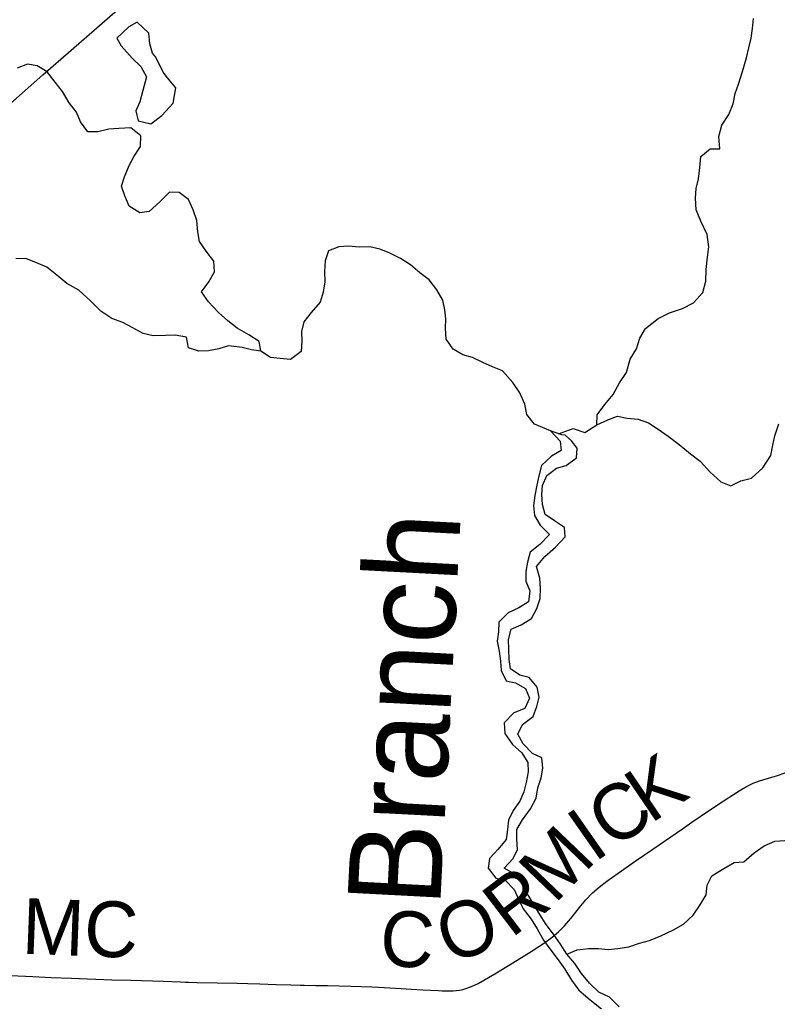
# Model space of a CAD drawing. Extents: x 0 to 34, y 0 to 22.
# Drawn here: x 26.924 to 27.697, y 10.604 to 11.606 of the extents above; entities that cross this region are included whole.
import ezdxf

# ---------------------------------------------------------------- set-up
doc = ezdxf.new("R2010")
doc.units = 0
for name, color, linetype in [('GM_X_County_Road', 7, 'Continuous'), ('GM_X_County_Road_Text', 7, 'Continuous'), ('GM_X_Minor_Lake', 7, 'Continuous'), ('GM_X_Minor_River', 7, 'Continuous'), ('GM_X_Minor_River_Text', 7, 'Continuous'), ('GM_X_Rail_Line', 7, 'Continuous')]:
    doc.layers.add(name, color=color, linetype=linetype)

msp = doc.modelspace()

# ---------------------------------------------------------------- linework, layer by layer
at = {"layer": 'GM_X_County_Road'}
msp.add_lwpolyline([(26.9075, 10.631), (26.938, 10.6298), (26.9565, 10.6289), (26.9772, 10.628), (27.0186, 10.6265), (27.0378, 10.6259), (27.0707, 10.625), (27.0887, 10.6243), (27.0937, 10.6241), (27.0967, 10.6241), (27.1054, 10.6237), (27.1463, 10.6229), (27.1572, 10.6227), (27.1696, 10.6222), (27.1863, 10.6215), (27.2012, 10.6212), (27.2105, 10.621), (27.2148, 10.6209), (27.2266, 10.6207), (27.2384, 10.6205), (27.2626, 10.62), (27.2837, 10.6192), (27.2905, 10.6189), (27.3135, 10.6176), (27.324, 10.6169), (27.3358, 10.6162), (27.3513, 10.6154), (27.3556, 10.6151), (27.3593, 10.615), (27.3627, 10.6151), (27.3666, 10.6152), (27.3699, 10.6154), (27.3732, 10.6158), (27.3766, 10.6164), (27.3798, 10.6175), (27.3855, 10.6196), (27.3921, 10.6228), (27.4093, 10.6325), (27.4214, 10.6399), (27.432, 10.6464), (27.4463, 10.6552), (27.4588, 10.6633), (27.4677, 10.6699), (27.4743, 10.6755), (27.4804, 10.6816), (27.4868, 10.6891), (27.4918, 10.6954), (27.4969, 10.7017), (27.5021, 10.7079), (27.509, 10.7151), (27.5156, 10.7209), (27.5234, 10.7271), (27.5351, 10.7353), (27.5442, 10.7418), (27.5523, 10.7475), (27.5703, 10.7597), (27.6006, 10.7804), (27.6102, 10.7872), (27.6282, 10.7995), (27.6422, 10.8087), (27.6584, 10.8193), (27.666, 10.8236), (27.6727, 10.8269), (27.6792, 10.8294), (27.6917, 10.8331), (27.6965, 10.8346), (27.7064, 10.8378)], dxfattribs=at)
at = {"layer": 'GM_X_Minor_Lake'}
msp.add_line((27.0707, 11.5522), (27.0633, 11.5677), dxfattribs=at)
msp.add_lwpolyline([(27.0633, 11.5677), (27.0598, 11.5718), (27.0571, 11.5813), (27.0562, 11.5919), (27.0443, 11.6032), (27.0357, 11.5985), (27.0237, 11.587), (27.0279, 11.579), (27.0391, 11.5666), (27.0479, 11.558), (27.0537, 11.5475), (27.05, 11.5337), (27.0471, 11.5219), (27.0431, 11.5128), (27.0455, 11.5026), (27.0584, 11.4997), (27.0696, 11.5082), (27.0812, 11.5208), (27.0837, 11.5364), (27.0753, 11.5466), (27.0707, 11.5522)], dxfattribs=at)
at = {"layer": 'GM_X_Minor_River'}
for points in [[(27.5133, 11.1925), (27.5136, 11.2028), (27.5214, 11.2131), (27.53, 11.2235), (27.5363, 11.2353), (27.5434, 11.246), (27.5474, 11.2594), (27.5537, 11.2701), (27.557, 11.2808), (27.5629, 11.2907), (27.5757, 11.3011), (27.5874, 11.3069), (27.6006, 11.3113), (27.6119, 11.3171), (27.6216, 11.3275), (27.6245, 11.3389), (27.6247, 11.351), (27.6261, 11.3636), (27.6275, 11.3742), (27.6259, 11.3867), (27.6193, 11.4003), (27.6146, 11.4117), (27.6141, 11.4238), (27.6147, 11.4337), (27.6169, 11.4436), (27.6183, 11.455), (27.6193, 11.4664), (27.629, 11.4741), (27.6389, 11.4742), (27.6376, 11.4867), (27.6409, 11.4981), (27.648, 11.5092), (27.6524, 11.5199), (27.6545, 11.5306), (27.6578, 11.5401), (27.6618, 11.5531), (27.6659, 11.5668), (27.6684, 11.577), (27.6709, 11.5869), (27.672, 11.5968), (27.673, 11.6071)], [(27.1705, 11.2675), (27.1688, 11.2774), (27.1581, 11.2844), (27.1463, 11.2911), (27.1368, 11.2986), (27.1272, 11.3072), (27.1172, 11.3181), (27.1099, 11.3283), (27.1174, 11.3383), (27.1233, 11.3486), (27.1225, 11.3596), (27.1148, 11.3697), (27.1078, 11.3795), (27.1062, 11.3894), (27.1053, 11.4008), (27.1014, 11.4117), (27.0967, 11.4223), (27.0872, 11.4294), (27.0773, 11.43), (27.0676, 11.4201), (27.0567, 11.4101), (27.0469, 11.4088), (27.0362, 11.4155), (27.0316, 11.4261), (27.0284, 11.4359), (27.0313, 11.4455), (27.0361, 11.4569), (27.0413, 11.4665), (27.0477, 11.4764), (27.0479, 11.4874), (27.038, 11.4956), (27.0255, 11.4947), (27.0153, 11.4942), (27.0043, 11.4915), (26.9941, 11.4913), (26.9864, 11.5015), (26.9825, 11.5113), (26.9748, 11.5211), (26.9682, 11.5324), (26.9606, 11.5422), (26.9525, 11.5527), (26.9422, 11.5587), (26.9323, 11.5605), (26.9218, 11.5565)], [(27.466, 11.1863), (27.4497, 11.1933), (27.442, 11.2031), (27.44, 11.2137), (27.4349, 11.225), (27.4276, 11.2356), (27.4169, 11.2476), (27.407, 11.2517), (27.3971, 11.2561), (27.3864, 11.2613), (27.3765, 11.2638), (27.3666, 11.2698), (27.3597, 11.28), (27.3588, 11.291), (27.3591, 11.3005), (27.3582, 11.3099), (27.3562, 11.3198), (27.35, 11.3303), (27.3423, 11.3405), (27.3328, 11.3476), (27.3232, 11.3559), (27.3129, 11.3622), (27.3015, 11.3681), (27.292, 11.3718), (27.2817, 11.374), (27.2707, 11.3738), (27.2601, 11.3749), (27.2499, 11.374), (27.2394, 11.3701), (27.2361, 11.3598), (27.2354, 11.3491), (27.2359, 11.3385), (27.2342, 11.3279), (27.2309, 11.3176), (27.2219, 11.3072), (27.2144, 11.2976), (27.2119, 11.2877), (27.2124, 11.2779), (27.2117, 11.2672), (27.2008, 11.2591), (27.1902, 11.2601), (27.1804, 11.2612), (27.1705, 11.2675), (27.161, 11.2689), (27.1515, 11.2715), (27.1374, 11.2732), (27.1276, 11.27), (27.117, 11.268), (27.1072, 11.2675), (27.0966, 11.2712), (27.0945, 11.2818), (27.0832, 11.284), (27.0733, 11.2835), (27.0608, 11.2833), (27.0506, 11.2858), (27.0391, 11.2918), (27.0296, 11.297), (27.0186, 11.301), (27.0071, 11.3085), (26.9968, 11.319), (26.9849, 11.3299), (26.9724, 11.3366), (26.9624, 11.3452), (26.9521, 11.3534), (26.9411, 11.3582), (26.9315, 11.3619), (26.9206, 11.3622)], [(27.4743, 11.1835), (27.4891, 11.1888), (27.5009, 11.1848), (27.5133, 11.1925), (27.5246, 11.1976), (27.5344, 11.2015), (27.5443, 11.1994), (27.5553, 11.1984), (27.5659, 11.1947), (27.5758, 11.188), (27.5861, 11.1809), (27.5972, 11.1726), (27.6087, 11.1629), (27.6186, 11.1554), (27.6286, 11.1445), (27.6397, 11.1344), (27.65, 11.1304), (27.6601, 11.1354), (27.6711, 11.1382), (27.6827, 11.1486), (27.6909, 11.1612), (27.6927, 11.1719), (27.6948, 11.1814), (27.6989, 11.1936)], [(27.5362, 10.599), (27.5263, 10.6087), (27.5153, 10.6139), (27.5057, 10.6229), (27.4976, 10.6327), (27.4907, 10.6429), (27.4826, 10.6527), (27.4761, 10.6628), (27.4691, 10.673), (27.4615, 10.6828), (27.4553, 10.693), (27.4483, 10.7047), (27.4422, 10.7145), (27.4383, 10.7243), (27.4298, 10.7341), (27.4188, 10.7404), (27.4281, 10.75), (27.4322, 10.7595), (27.4317, 10.7698), (27.4316, 10.7796), (27.4375, 10.7896), (27.4457, 10.8007), (27.4513, 10.8118), (27.4531, 10.8224), (27.4564, 10.8323), (27.4582, 10.8422), (27.4573, 10.8528), (27.4478, 10.8573), (27.4382, 10.867), (27.4328, 10.8769), (27.4376, 10.8868), (27.4485, 10.8949), (27.4521, 10.9052), (27.4543, 10.9147), (27.4523, 10.9249), (27.4442, 10.9347), (27.4347, 10.9372), (27.4252, 10.9436), (27.424, 10.9531), (27.423, 10.9736), (27.4259, 10.9842), (27.4361, 10.9885), (27.4466, 10.9951), (27.4522, 11.005), (27.4554, 11.0153), (27.4557, 11.0256), (27.4552, 11.0362), (27.4517, 11.0479), (27.4603, 11.0583), (27.4711, 11.0679), (27.4809, 11.0783), (27.4804, 11.0878), (27.4701, 11.0945), (27.4605, 11.1012), (27.4578, 11.1114), (27.4573, 11.1213), (27.4579, 11.1308), (27.4624, 11.1407), (27.4721, 11.1484), (27.4819, 11.1512), (27.4925, 11.1589), (27.4931, 11.1688), (27.4875, 11.1761), (27.481, 11.1819), (27.4776, 11.1824), (27.466, 11.1863), (27.476, 11.1758), (27.4769, 11.1663), (27.4671, 11.1605), (27.457, 11.1509), (27.454, 11.1406), (27.4522, 11.1311), (27.4501, 11.1204), (27.4487, 11.1102), (27.4496, 11.0999), (27.4554, 11.0901), (27.4649, 11.0807), (27.4552, 11.0704), (27.4454, 11.0627), (27.4425, 11.0524), (27.4407, 11.0429), (27.4409, 11.033), (27.4451, 11.0232), (27.4437, 11.0118), (27.4336, 11.006), (27.4227, 11.0009), (27.4133, 10.9913), (27.413, 10.9814), (27.4116, 10.9719), (27.4136, 10.9617), (27.4149, 10.9514), (27.4157, 10.942), (27.4208, 10.9314), (27.4303, 10.9292), (27.4406, 10.9236), (27.4445, 10.9138), (27.4397, 10.9031), (27.4287, 10.8988), (27.4186, 10.8885), (27.4195, 10.8778)], [(27.4195, 10.8778), (27.4272, 10.8665), (27.4368, 10.8579), (27.4429, 10.8481), (27.4434, 10.8386), (27.4413, 10.8276), (27.4387, 10.8181), (27.4347, 10.8085), (27.428, 10.799), (27.4231, 10.7894), (27.4221, 10.7799), (27.4207, 10.7696), (27.4125, 10.7597), (27.4039, 10.7501), (27.4025, 10.7402), (27.4102, 10.73), (27.4197, 10.7282), (27.4289, 10.7185), (27.4335, 10.7087), (27.4382, 10.6988), (27.4462, 10.6883), (27.4524, 10.6785), (27.459, 10.6668), (27.4663, 10.6566), (27.474, 10.6469), (27.4805, 10.6371), (27.4875, 10.6261), (27.4948, 10.616), (27.5066, 10.6059), (27.5181, 10.5969)], [(27.4826, 10.6527), (27.4932, 10.657), (27.5049, 10.6582), (27.5151, 10.6584), (27.525, 10.6573), (27.5348, 10.6582), (27.5458, 10.6602), (27.5567, 10.6638), (27.5669, 10.6666), (27.5786, 10.6713), (27.5914, 10.6775), (27.6016, 10.6833), (27.6117, 10.6925), (27.6188, 10.7029), (27.6247, 10.7132), (27.6257, 10.7231), (27.6306, 10.7326), (27.643, 10.74), (27.6535, 10.7462), (27.6634, 10.7467), (27.6739, 10.7559), (27.684, 10.7632), (27.6949, 10.7679), (27.7052, 10.7684)]]:
    msp.add_lwpolyline(points, dxfattribs=at)
at = {"layer": 'GM_X_Rail_Line'}
msp.add_lwpolyline([(26.8817, 11.4912), (26.9482, 11.5494), (27.0059, 11.6), (27.066, 11.6527)], dxfattribs=at)

# ---------------------------------------------------------------- texts
at = {"layer": 'GM_X_County_Road_Text'}
for s, height, rotation, p in [('K', 0.0568, 34.1689, (27.5682, 10.785)), ('C', 0.0568, 34.2508, (27.5296, 10.7587)), ('I', 0.0568, 35.0086, (27.5107, 10.7455)), ('M', 0.0568, 46.1898, (27.4702, 10.7029)), ('R', 0.0568, 37.3717, (27.426, 10.6682)), ('MC', 0.05682, 357.8134, (26.9261, 10.6531)), ('O', 0.0568, 20.1469, (27.3628, 10.642)), ('C', 0.0568, 356.2231, (27.2907, 10.6414))]:
    msp.add_text(s, height=height, rotation=rotation, dxfattribs=at).set_placement(p)
at = {"layer": 'GM_X_Minor_River_Text'}
msp.add_text('Branch', height=0.09473, rotation=86.9762, dxfattribs=at).set_placement((27.3533, 10.6999))

doc.saveas('drawing.dxf')
